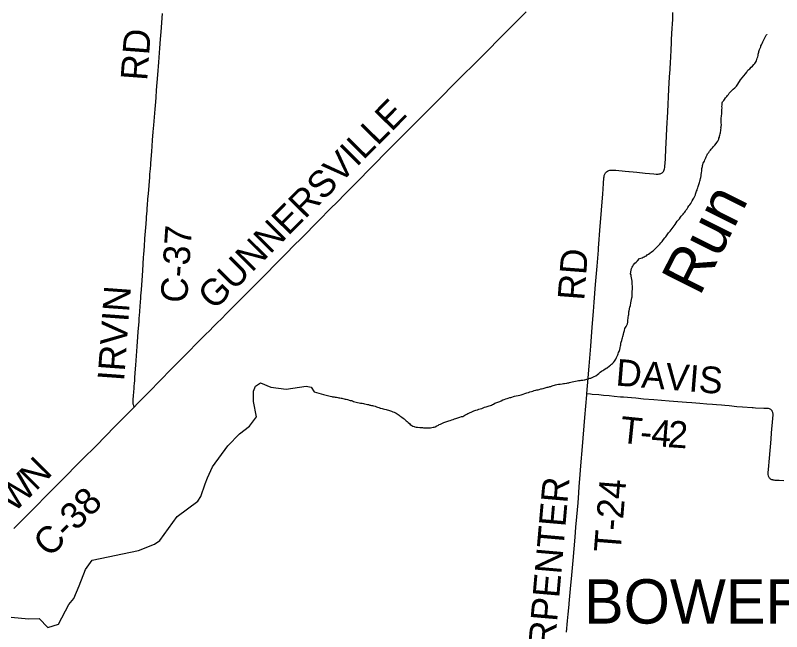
# Model space of a CAD drawing. Extents: x -49 to -8.2, y 9.4 to 23.5.
# Drawn here: x -13.07 to -12.253, y 10.162 to 10.819 of the extents above; entities that cross this region are included whole.
import ezdxf

# ---------------------------------------------------------------- set-up
doc = ezdxf.new("R2010")
doc.units = 0
for name, color, linetype in [('GM_X_Corporation_Text', 7, 'Continuous'), ('GM_X_County_Road', 7, 'Continuous'), ('GM_X_County_Road_Text', 7, 'Continuous'), ('GM_X_Minor_River', 7, 'Continuous'), ('GM_X_Minor_River_Text', 7, 'Continuous'), ('GM_X_Township_Road', 7, 'Continuous'), ('GM_X_Township_Road_Text', 7, 'Continuous')]:
    doc.layers.add(name, color=color, linetype=linetype)

msp = doc.modelspace()

# ---------------------------------------------------------------- linework, layer by layer
at = {"layer": 'GM_X_County_Road'}
for points in [[(-12.94372, 10.4013), (-12.94414, 10.40283), (-12.94457, 10.40442), (-12.94471, 10.40504), (-12.94479, 10.40577), (-12.94471, 10.40743), (-12.94458, 10.40915), (-12.94425, 10.41312), (-12.94392, 10.41743), (-12.94381, 10.41866), (-12.94375, 10.41988), (-12.9435, 10.42359), (-12.94326, 10.42637), (-12.94307, 10.42946), (-12.94278, 10.43287), (-12.94216, 10.44185), (-12.94188, 10.44588), (-12.94109, 10.45579), (-12.94077, 10.46075), (-12.94037, 10.46571), (-12.93968, 10.47624), (-12.93927, 10.48151), (-12.93842, 10.49235), (-12.93816, 10.49606), (-12.93798, 10.49885), (-12.93761, 10.50318), (-12.93721, 10.50874), (-12.93655, 10.51741), (-12.93638, 10.51989), (-12.93598, 10.52613), (-12.93489, 10.54157), (-12.93453, 10.5469), (-12.93364, 10.56081), (-12.93341, 10.56422), (-12.93278, 10.57226), (-12.93208, 10.58094), (-12.93096, 10.59674), (-12.93063, 10.60201), (-12.93044, 10.60449), (-12.93021, 10.60696), (-12.92994, 10.61067), (-12.92968, 10.61345), (-12.9295, 10.61593), (-12.92891, 10.62304), (-12.92848, 10.6286), (-12.92775, 10.63758), (-12.92701, 10.64624), (-12.92676, 10.64934), (-12.92649, 10.65243), (-12.92631, 10.65522), (-12.92598, 10.65956), (-12.9259, 10.6611), (-12.92489, 10.6738), (-12.92447, 10.67937), (-12.92396, 10.68588), (-12.92325, 10.69455), (-12.92272, 10.70167), (-12.92134, 10.71871), (-12.92065, 10.72675), (-12.92026, 10.73139), (-12.91969, 10.73914), (-12.91848, 10.75525), (-12.91741, 10.76888), (-12.91628, 10.78374), (-12.91553, 10.79335), (-12.91493, 10.80109), (-12.91358, 10.82062)], [(-12.62822, 10.71985), (-12.61749, 10.73061), (-12.60264, 10.74564), (-12.5725, 10.7757), (-12.54884, 10.79949), (-12.5359, 10.81247), (-12.52586, 10.82264)], [(-12.94372, 10.4013), (-12.94004, 10.4051), (-12.93259, 10.41259), (-12.92407, 10.4212), (-12.9195, 10.42587), (-12.91296, 10.43251), (-12.90688, 10.43872), (-12.90014, 10.4456), (-12.89446, 10.45135), (-12.88463, 10.46129), (-12.8779, 10.46818), (-12.87353, 10.4726), (-12.86786, 10.47835), (-12.86278, 10.48337), (-12.85968, 10.48643), (-12.85506, 10.49104), (-12.85068, 10.49543), (-12.84521, 10.50094), (-12.83251, 10.51374), (-12.82502, 10.52118), (-12.81053, 10.53569), (-12.80266, 10.54364), (-12.79327, 10.55314), (-12.78866, 10.55776), (-12.78164, 10.5648), (-12.77292, 10.57365), (-12.76591, 10.58071), (-12.74603, 10.60081), (-12.73491, 10.61209), (-12.72661, 10.62049), (-12.71937, 10.62776), (-12.70775, 10.63942), (-12.68928, 10.65828), (-12.67343, 10.67452), (-12.6609, 10.68704), (-12.65432, 10.69363), (-12.6519, 10.69605), (-12.63833, 10.70971), (-12.62822, 10.71985)], [(-13.07176, 10.27187), (-13.06437, 10.27945), (-13.04942, 10.29437), (-13.03642, 10.30772), (-13.02393, 10.32028), (-13.01512, 10.32905), (-13.00639, 10.33789), (-12.99874, 10.34562), (-12.9842, 10.36008), (-12.96411, 10.3804), (-12.9489, 10.39595), (-12.94372, 10.4013)]]:
    msp.add_lwpolyline(points, dxfattribs=at)
at = {"layer": 'GM_X_Minor_River'}
for points in [[(-12.31105, 10.73325), (-12.31027, 10.73438), (-12.30929, 10.73569), (-12.30793, 10.73719), (-12.30637, 10.73887), (-12.30502, 10.74018), (-12.30347, 10.74148), (-12.3025, 10.74223), (-12.30172, 10.74335), (-12.30093, 10.74448), (-12.30015, 10.74542), (-12.29721, 10.74993), (-12.29565, 10.75219), (-12.29389, 10.75444), (-12.29214, 10.7565), (-12.29058, 10.75818), (-12.2894, 10.76025), (-12.28746, 10.76193), (-12.28591, 10.76342), (-12.28455, 10.76473), (-12.283, 10.76642), (-12.28222, 10.76735), (-12.28143, 10.76867), (-12.28045, 10.77018), (-12.28004, 10.77169), (-12.27944, 10.7732), (-12.27904, 10.77453), (-12.27863, 10.77604), (-12.27841, 10.77737), (-12.2782, 10.77832), (-12.2778, 10.77945), (-12.27778, 10.7804), (-12.27758, 10.78135), (-12.27717, 10.78249), (-12.27639, 10.7838), (-12.27579, 10.78512), (-12.27558, 10.78645), (-12.27499, 10.78739), (-12.27439, 10.78871), (-12.2736, 10.79041), (-12.273, 10.79192), (-12.27202, 10.79343), (-12.26984, 10.79776), (-12.26926, 10.79832), (-12.26926, 10.79813)], [(-12.36478, 10.5995), (-12.36342, 10.60081), (-12.36245, 10.60174), (-12.36127, 10.60362), (-12.36049, 10.60456), (-12.35952, 10.60569), (-12.35854, 10.607), (-12.35776, 10.60794), (-12.35679, 10.60906), (-12.35601, 10.61019), (-12.35522, 10.61151), (-12.35425, 10.61263), (-12.35346, 10.61395), (-12.35228, 10.61564), (-12.35131, 10.61676), (-12.35033, 10.61827), (-12.34973, 10.61959), (-12.34875, 10.62109), (-12.34777, 10.62298), (-12.34699, 10.62391), (-12.34639, 10.62524), (-12.34599, 10.62618), (-12.3454, 10.62731), (-12.34519, 10.62826), (-12.34498, 10.62921), (-12.34458, 10.63034), (-12.34437, 10.63129), (-12.34359, 10.63261), (-12.34338, 10.63355), (-12.34278, 10.63488), (-12.34237, 10.63639), (-12.34136, 10.63961), (-12.34096, 10.64055), (-12.34075, 10.64188), (-12.34034, 10.6432), (-12.33993, 10.64472), (-12.33972, 10.64605), (-12.33931, 10.64775), (-12.33909, 10.64908), (-12.33887, 10.65079), (-12.33864, 10.65288), (-12.33862, 10.65421), (-12.3384, 10.65554), (-12.33819, 10.65668), (-12.33798, 10.65762), (-12.33777, 10.65857), (-12.33756, 10.65971), (-12.33715, 10.66122), (-12.33578, 10.66348), (-12.33537, 10.66462), (-12.33458, 10.66612), (-12.33438, 10.66707), (-12.33398, 10.66802), (-12.33338, 10.66934), (-12.33279, 10.67028), (-12.33239, 10.67122), (-12.33123, 10.67253), (-12.33044, 10.67404), (-12.32947, 10.67497), (-12.32849, 10.67629), (-12.32732, 10.6776), (-12.32596, 10.67891), (-12.3246, 10.68059), (-12.32324, 10.68209), (-12.32245, 10.68322), (-12.32166, 10.68473), (-12.32088, 10.68604), (-12.32029, 10.68698), (-12.32027, 10.68794), (-12.31987, 10.68888), (-12.31966, 10.68983), (-12.31926, 10.69115), (-12.31904, 10.69248), (-12.31883, 10.69343), (-12.31821, 10.69627), (-12.31838, 10.69723), (-12.31798, 10.69836), (-12.31815, 10.69932), (-12.31794, 10.70045), (-12.31772, 10.70197), (-12.31807, 10.70407), (-12.31803, 10.70616), (-12.3178, 10.70806), (-12.31797, 10.70959), (-12.31775, 10.71111), (-12.31754, 10.71205), (-12.31733, 10.71338), (-12.3173, 10.71471), (-12.31727, 10.71624), (-12.31724, 10.71814), (-12.31701, 10.72004), (-12.31717, 10.72156), (-12.31696, 10.72289), (-12.31694, 10.72422), (-12.31691, 10.72555), (-12.31651, 10.72669), (-12.31515, 10.728), (-12.31437, 10.72893), (-12.31319, 10.73082), (-12.31183, 10.73231), (-12.31105, 10.73325)], [(-12.44316, 10.44109), (-12.44047, 10.44256), (-12.43951, 10.44312), (-12.4368, 10.44516), (-12.43583, 10.4459), (-12.43486, 10.44683), (-12.43389, 10.44777), (-12.43273, 10.44889), (-12.43175, 10.4502), (-12.43038, 10.45246), (-12.42958, 10.45416), (-12.42879, 10.45567), (-12.4282, 10.4568), (-12.4276, 10.45812), (-12.4272, 10.45945), (-12.4268, 10.46039), (-12.4264, 10.46152), (-12.426, 10.46247), (-12.42558, 10.46436), (-12.42516, 10.46645), (-12.42495, 10.46759), (-12.42473, 10.4693), (-12.42452, 10.47043), (-12.42391, 10.47233), (-12.42331, 10.47403), (-12.4231, 10.47497), (-12.42269, 10.47649), (-12.42207, 10.47914), (-12.42166, 10.48085), (-12.42105, 10.48274), (-12.42063, 10.48501), (-12.41926, 10.48708), (-12.41847, 10.4884), (-12.41787, 10.4901), (-12.41746, 10.49181), (-12.41743, 10.49314), (-12.41699, 10.49656), (-12.41676, 10.49884), (-12.41654, 10.49997), (-12.41651, 10.50169), (-12.4163, 10.50263), (-12.41609, 10.50377), (-12.41545, 10.50776), (-12.41465, 10.50946), (-12.41422, 10.51249), (-12.41358, 10.51591), (-12.41317, 10.5178), (-12.41296, 10.51875), (-12.41293, 10.52027), (-12.41271, 10.52179), (-12.41268, 10.52331), (-12.41285, 10.52484), (-12.41262, 10.52654), (-12.41239, 10.52863), (-12.41255, 10.53054), (-12.41271, 10.53207), (-12.41288, 10.5334), (-12.41284, 10.5353), (-12.41319, 10.53721), (-12.41354, 10.53912), (-12.4137, 10.54084), (-12.41405, 10.54218), (-12.41441, 10.54332), (-12.41396, 10.54731), (-12.41355, 10.54883), (-12.41295, 10.55034), (-12.41217, 10.55128), (-12.41138, 10.55278), (-12.40982, 10.55466), (-12.40847, 10.55578), (-12.40729, 10.55728), (-12.40516, 10.55952), (-12.40228, 10.56023), (-12.40094, 10.56096), (-12.39998, 10.56133), (-12.39882, 10.56207), (-12.39767, 10.56262), (-12.3967, 10.56336), (-12.39554, 10.5641), (-12.394, 10.56521), (-12.39206, 10.5667), (-12.39033, 10.56781), (-12.38897, 10.56912), (-12.38683, 10.57136), (-12.38489, 10.57342), (-12.38334, 10.57491), (-12.38217, 10.57642), (-12.38081, 10.57772), (-12.38003, 10.57866), (-12.37924, 10.57979), (-12.37807, 10.58148), (-12.3769, 10.58279), (-12.37397, 10.58692), (-12.37222, 10.5886), (-12.37124, 10.59011), (-12.37007, 10.59142), (-12.36909, 10.59292), (-12.36811, 10.59443), (-12.36713, 10.59593), (-12.36596, 10.59762), (-12.36478, 10.5995)], [(-12.60059, 10.38918), (-12.59848, 10.3899), (-12.59657, 10.39043), (-12.59484, 10.39116), (-12.59331, 10.39133), (-12.59235, 10.39188), (-12.591, 10.39262), (-12.58985, 10.39317), (-12.58889, 10.39372), (-12.58792, 10.39427), (-12.58677, 10.39482), (-12.58312, 10.39647), (-12.58158, 10.3972), (-12.57947, 10.39792), (-12.57774, 10.39846), (-12.57621, 10.399), (-12.57468, 10.39936), (-12.57295, 10.3999), (-12.57161, 10.40044), (-12.57007, 10.40099), (-12.56854, 10.40134), (-12.5672, 10.40169), (-12.56624, 10.40225), (-12.56528, 10.40242), (-12.56394, 10.40296), (-12.56279, 10.40313), (-12.56163, 10.40387), (-12.56048, 10.40423), (-12.55913, 10.40554), (-12.55587, 10.40643), (-12.55395, 10.40716), (-12.55241, 10.40789), (-12.55049, 10.40881), (-12.54934, 10.40936), (-12.54761, 10.4099), (-12.54608, 10.41044), (-12.54493, 10.4108), (-12.5432, 10.41134), (-12.54205, 10.41151), (-12.53822, 10.41277), (-12.53631, 10.41311), (-12.53439, 10.41365), (-12.53267, 10.414), (-12.53095, 10.41435), (-12.52903, 10.41488), (-12.5273, 10.41561), (-12.52519, 10.41633), (-12.52328, 10.41668), (-12.52193, 10.41742), (-12.52021, 10.41796), (-12.51868, 10.41831), (-12.51714, 10.41885), (-12.51561, 10.41939), (-12.51446, 10.41956), (-12.51312, 10.41973), (-12.51197, 10.42009), (-12.51025, 10.42063), (-12.50929, 10.4208), (-12.50776, 10.42115), (-12.50661, 10.42151), (-12.50546, 10.42168), (-12.50431, 10.42204), (-12.50335, 10.4224), (-12.5024, 10.42258), (-12.50144, 10.42294), (-12.50048, 10.42311), (-12.49953, 10.42328), (-12.49799, 10.42383), (-12.49684, 10.42419), (-12.49569, 10.42455), (-12.49454, 10.42491), (-12.4932, 10.42526), (-12.49148, 10.42561), (-12.48938, 10.42576), (-12.48728, 10.4261), (-12.48594, 10.42627), (-12.48479, 10.42644), (-12.4825, 10.42678), (-12.48135, 10.42714), (-12.4804, 10.42712), (-12.47944, 10.42748), (-12.4781, 10.42784), (-12.47676, 10.428), (-12.4714, 10.42924), (-12.46987, 10.42959), (-12.46815, 10.42956), (-12.467, 10.42992), (-12.46547, 10.43008), (-12.46414, 10.43025), (-12.46318, 10.43042), (-12.45992, 10.4315), (-12.45782, 10.43203), (-12.45686, 10.43221), (-12.4534, 10.43367), (-12.45148, 10.43439), (-12.44993, 10.43588), (-12.44819, 10.43718), (-12.44684, 10.4383), (-12.44548, 10.43961), (-12.44413, 10.44035), (-12.44316, 10.44109)], [(-13.07478, 10.17736), (-13.05621, 10.17541), (-13.04483, 10.17602), (-13.03565, 10.16641), (-13.02442, 10.16987), (-13.01336, 10.1908), (-13.00778, 10.19718), (-13.00504, 10.20398), (-13.00212, 10.21078), (-12.99565, 10.22796), (-12.98833, 10.23812), (-12.93889, 10.24849), (-12.92212, 10.25511), (-12.91638, 10.25921), (-12.89787, 10.28459), (-12.87568, 10.30101), (-12.87239, 10.3059), (-12.86806, 10.31951), (-12.86533, 10.32593), (-12.86007, 10.33744), (-12.84368, 10.36001), (-12.83139, 10.37275), (-12.82067, 10.38078), (-12.81315, 10.39093), (-12.81637, 10.40729), (-12.81643, 10.41811), (-12.81447, 10.42359), (-12.80912, 10.42694), (-12.79798, 10.42262), (-12.7817, 10.42051), (-12.76023, 10.42346), (-12.75493, 10.42244), (-12.75177, 10.41747), (-12.74177, 10.41482)], [(-12.74177, 10.41482), (-12.73472, 10.41277), (-12.73301, 10.41235), (-12.73206, 10.41234), (-12.73054, 10.41212), (-12.72921, 10.4119), (-12.72807, 10.41169), (-12.72636, 10.41147), (-12.72541, 10.41126), (-12.72446, 10.41106), (-12.72313, 10.41065), (-12.72218, 10.41063), (-12.72123, 10.41043), (-12.71971, 10.41021), (-12.71876, 10.40981), (-12.71762, 10.4096), (-12.7163, 10.40919), (-12.71326, 10.40838), (-12.71212, 10.40816), (-12.7108, 10.40776), (-12.70966, 10.40736), (-12.70833, 10.40695), (-12.70682, 10.40655), (-12.70549, 10.40614), (-12.70397, 10.40592), (-12.70245, 10.40551), (-12.70074, 10.40529), (-12.69922, 10.40507), (-12.69808, 10.40486), (-12.69618, 10.40445), (-12.69505, 10.40404), (-12.69372, 10.40383), (-12.69258, 10.40343), (-12.69163, 10.40322), (-12.69068, 10.40301), (-12.68954, 10.4028), (-12.68841, 10.4024), (-12.68688, 10.40218), (-12.68537, 10.40158), (-12.68424, 10.40118), (-12.6829, 10.40097), (-12.68158, 10.40018), (-12.68064, 10.39997), (-12.67912, 10.39956), (-12.67817, 10.39936), (-12.67665, 10.39895), (-12.67513, 10.39854), (-12.67399, 10.39833), (-12.67267, 10.39811), (-12.67153, 10.39771), (-12.66926, 10.39691), (-12.66775, 10.39612), (-12.66661, 10.39572), (-12.66567, 10.39532), (-12.66434, 10.39473), (-12.66321, 10.39394), (-12.66133, 10.39258), (-12.66039, 10.3918), (-12.65945, 10.39121), (-12.65832, 10.39043), (-12.65701, 10.38926), (-12.65588, 10.38867), (-12.65494, 10.3877), (-12.65382, 10.38654), (-12.6525, 10.38575), (-12.65156, 10.38478), (-12.65025, 10.38362), (-12.64931, 10.38284), (-12.64762, 10.38148), (-12.64668, 10.38108), (-12.64535, 10.38048), (-12.64441, 10.38009), (-12.64289, 10.37987), (-12.64174, 10.37985), (-12.63908, 10.37961), (-12.63737, 10.37958), (-12.63642, 10.37937), (-12.63528, 10.37916), (-12.63432, 10.37914), (-12.63337, 10.37912), (-12.63128, 10.37908), (-12.63013, 10.37906), (-12.62918, 10.37923), (-12.62784, 10.37921), (-12.6265, 10.37957), (-12.62497, 10.37973), (-12.62383, 10.3799), (-12.62268, 10.38026), (-12.62094, 10.38137), (-12.6194, 10.3821), (-12.61844, 10.38265), (-12.6171, 10.3832), (-12.61364, 10.38466), (-12.61153, 10.38557), (-12.60942, 10.3861), (-12.60807, 10.38665), (-12.60673, 10.38701), (-12.6052, 10.38755), (-12.60366, 10.38809), (-12.60213, 10.38863), (-12.60059, 10.38918)]]:
    msp.add_lwpolyline(points, dxfattribs=at)
at = {"layer": 'GM_X_Township_Road'}
for points in [[(-12.38654, 10.64961), (-12.38616, 10.6496), (-12.38527, 10.64962), (-12.38401, 10.64972), (-12.38312, 10.64992), (-12.38233, 10.65019), (-12.38169, 10.6505), (-12.38091, 10.65093), (-12.38013, 10.65154), (-12.37954, 10.65217), (-12.37891, 10.65318), (-12.37855, 10.6541), (-12.37818, 10.65527), (-12.37803, 10.65664), (-12.37786, 10.65807), (-12.37765, 10.66123), (-12.37743, 10.66584), (-12.37693, 10.67669), (-12.37667, 10.68228), (-12.37579, 10.69809), (-12.37484, 10.71609), (-12.37356, 10.73998), (-12.37286, 10.75331), (-12.37242, 10.76115), (-12.37192, 10.76924), (-12.37167, 10.77366), (-12.37117, 10.78276), (-12.3709, 10.78865), (-12.37071, 10.79269), (-12.3704, 10.79932), (-12.37019, 10.80476), (-12.36993, 10.80975), (-12.36963, 10.8144), (-12.3693, 10.82174)], [(-12.44865, 10.5707), (-12.44682, 10.59404), (-12.44575, 10.60642), (-12.44504, 10.61571), (-12.44424, 10.62811), (-12.44337, 10.63957), (-12.44297, 10.64549), (-12.44275, 10.64678), (-12.44255, 10.64793), (-12.44229, 10.6488), (-12.442, 10.64956), (-12.44166, 10.65019), (-12.44115, 10.65095), (-12.44069, 10.65154), (-12.4401, 10.65204), (-12.43897, 10.65275), (-12.43784, 10.65325), (-12.43666, 10.65361), (-12.43576, 10.65377), (-12.4348, 10.65387), (-12.43262, 10.65386), (-12.43014, 10.65369), (-12.42024, 10.65276), (-12.41653, 10.65243), (-12.41592, 10.65232), (-12.4119, 10.65194), (-12.40769, 10.65154), (-12.39891, 10.65073), (-12.38962, 10.64981), (-12.38712, 10.64964), (-12.38654, 10.64961)], [(-12.46115, 10.41571), (-12.46042, 10.42405), (-12.45865, 10.44478), (-12.4569, 10.46614), (-12.45529, 10.48627), (-12.45398, 10.50299), (-12.45323, 10.51322), (-12.45174, 10.53179), (-12.45024, 10.55162), (-12.44884, 10.56834), (-12.44865, 10.5707)], [(-12.48277, 10.1613), (-12.4817, 10.17336), (-12.48136, 10.17707), (-12.48105, 10.18047), (-12.48007, 10.19068), (-12.47995, 10.19191), (-12.47843, 10.20768), (-12.47707, 10.22222), (-12.47574, 10.23769), (-12.47356, 10.26245), (-12.47272, 10.27329), (-12.47178, 10.28412), (-12.47048, 10.29928), (-12.4697, 10.30981), (-12.46923, 10.31663), (-12.4686, 10.32468), (-12.46738, 10.3386), (-12.46567, 10.35934), (-12.46318, 10.38999), (-12.46227, 10.40208), (-12.46128, 10.41414), (-12.46115, 10.41571)], [(-12.46115, 10.41571), (-12.45711, 10.41532), (-12.45556, 10.41518), (-12.44845, 10.41448), (-12.44351, 10.41401), (-12.43732, 10.41346), (-12.43207, 10.41294), (-12.42527, 10.41233), (-12.42217, 10.41211), (-12.41352, 10.41143), (-12.40889, 10.41097), (-12.40085, 10.4102), (-12.38971, 10.40924), (-12.37331, 10.4079), (-12.35473, 10.40648), (-12.34915, 10.40606), (-12.34079, 10.40548), (-12.33337, 10.40486), (-12.32718, 10.40435), (-12.32285, 10.40396), (-12.31769, 10.4035)], [(-12.31769, 10.4035), (-12.31388, 10.40316), (-12.30955, 10.40279), (-12.3012, 10.40203), (-12.29532, 10.40153), (-12.28478, 10.40081), (-12.28386, 10.40073), (-12.28138, 10.40058), (-12.27241, 10.40023), (-12.26863, 10.40005), (-12.26787, 10.39992), (-12.26681, 10.39965), (-12.26609, 10.39938), (-12.26542, 10.39899), (-12.26494, 10.39862), (-12.26456, 10.39826), (-12.26409, 10.39774), (-12.26379, 10.39726), (-12.26349, 10.39666), (-12.26321, 10.39579), (-12.26309, 10.39522), (-12.26299, 10.39456), (-12.26294, 10.39383), (-12.26294, 10.393), (-12.26326, 10.38896), (-12.26459, 10.3738), (-12.26514, 10.36699), (-12.26692, 10.34688), (-12.268, 10.33481), (-12.26826, 10.33138), (-12.26825, 10.33024), (-12.26819, 10.32921), (-12.26792, 10.328), (-12.26761, 10.32715), (-12.26725, 10.32646), (-12.26679, 10.32585), (-12.26625, 10.32534), (-12.26562, 10.32487), (-12.2651, 10.32454), (-12.26413, 10.32411), (-12.2634, 10.32388), (-12.26275, 10.32377), (-12.2619, 10.32361), (-12.26058, 10.3235), (-12.25622, 10.32328), (-12.25107, 10.32292)]]:
    msp.add_lwpolyline(points, dxfattribs=at)

# ---------------------------------------------------------------- texts
at = {"layer": 'GM_X_Corporation_Text'}
msp.add_text('BOWERSVILLE', height=0.0473485, rotation=0.00001, dxfattribs=at).set_placement((-12.46412, 10.17044))
at = {"layer": 'GM_X_County_Road_Text'}
for s, height, rotation, p in [('RD', 0.028409, 85.66763, (-12.9298, 10.74862)), ('GUNNERSVILLE', 0.0284091, 45.24835, (-12.85827, 10.50361)), ('C-37', 0.028409, 86.23141, (-12.88732, 10.51169)), ('IRVIN', 0.028409, 85.86221, (-12.95438, 10.4283)), ('N', 0.02841, 45.20993, (-13.04856, 10.31103)), ('W', 0.02841, 45.23378, (-13.07174, 10.28766)), ('C-38', 0.028409, 45.23814, (-13.03378, 10.23998))]:
    msp.add_text(s, height=height, rotation=rotation, dxfattribs=at).set_placement(p)
at = {"layer": 'GM_X_Minor_River_Text'}
msp.add_text('Run', height=0.047343, rotation=63.21074, dxfattribs=at).set_placement((-12.34094, 10.5184))
at = {"layer": 'GM_X_Township_Road_Text'}
for s, height, rotation, p in [('RD', 0.028409, 85.60093, (-12.46398, 10.51435)), ('DAVIS', 0.028409, 355.32807, (-12.431, 10.42437)), ('T', 0.02841, 354.11201, (-12.42672, 10.36337)), ('4', 0.02841, 355.43814, (-12.39325, 10.36006)), ('2', 0.02841, 355.96894, (-12.37552, 10.35865)), ('-', 0.02841, 354.81158, (-12.40521, 10.36115)), ('CARPENTER', 0.028409, 85.02509, (-12.4998, 10.09209)), ('T-24', 0.028409, 85.41062, (-12.42531, 10.2456))]:
    msp.add_text(s, height=height, rotation=rotation, dxfattribs=at).set_placement(p)

doc.saveas('drawing.dxf')
